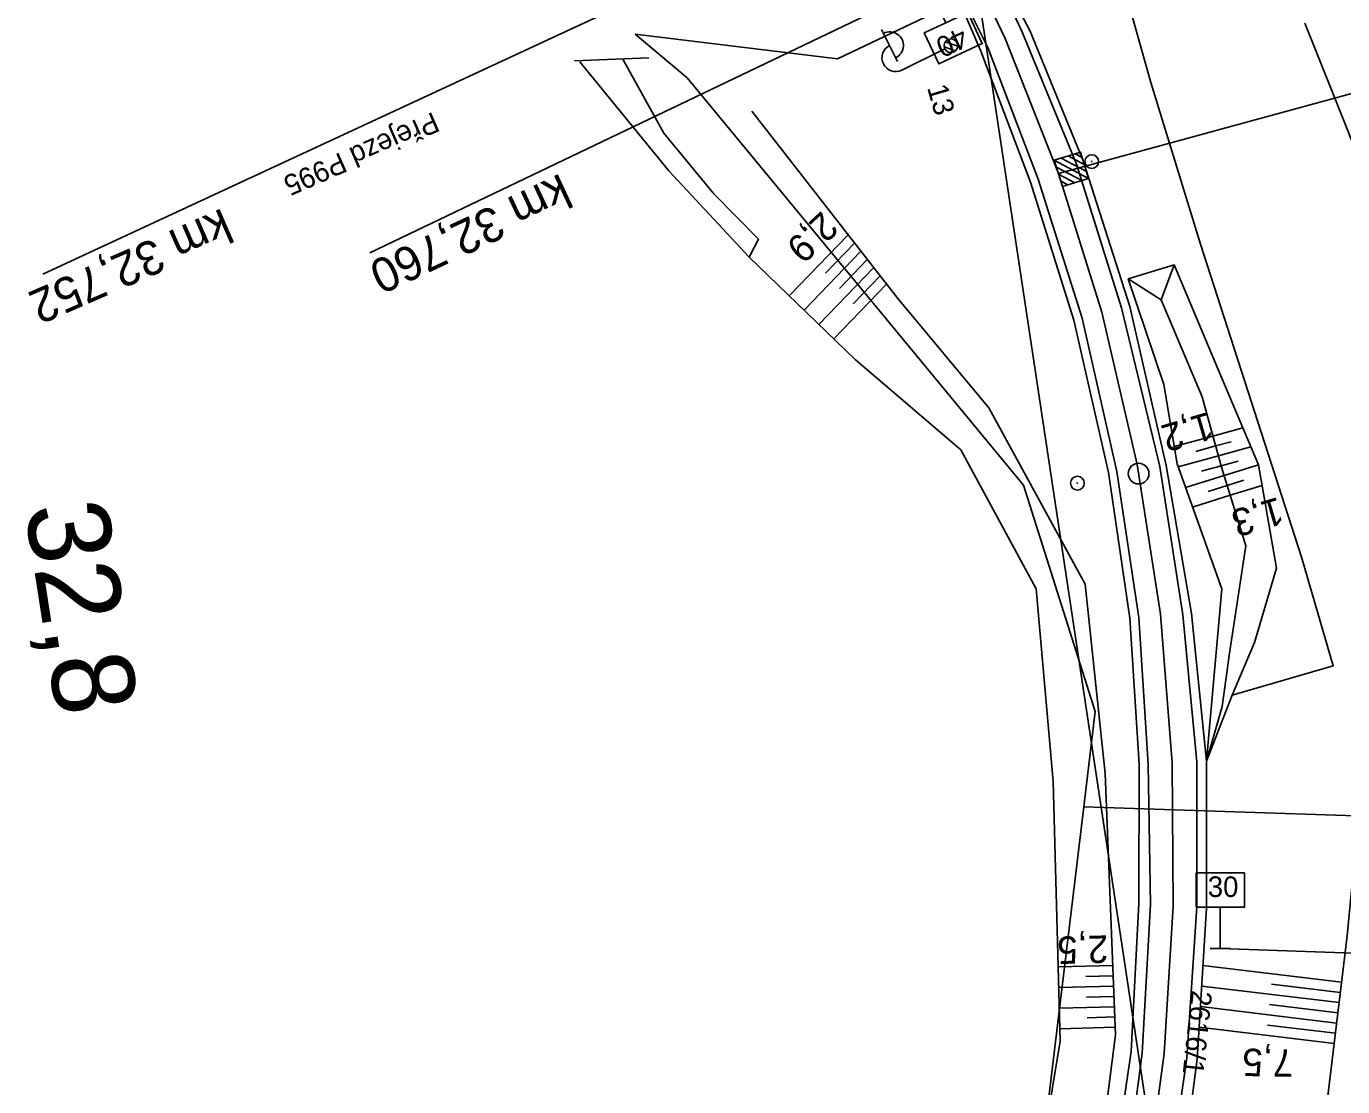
# Model space of a CAD drawing. Extents: x -804166 to -803706, y -1151030 to -1150147.
# Drawn here: x -803941 to -803845.1, y -1150593.1 to -1150515.9 of the extents above; entities that cross this region are included whole.
import ezdxf

# ---------------------------------------------------------------- set-up
doc = ezdxf.new("R2010")
doc.units = 0
for name, color, linetype in [('0381KM032-037P - Vrstva 1', 7, 'Continuous'), ('0381KM032-037P - Vrstva 16', 7, 'Continuous'), ('0381KM032-037P - Vrstva 25', 7, 'Continuous'), ('0381KM032-037P - Vrstva 27', 7, 'Continuous'), ('0381KM032-037P - Vrstva 3', 7, 'Continuous'), ('0381KM032-037P - Vrstva 4', 7, 'Continuous'), ('0381KM032-037P - Vrstva 48', 7, 'Continuous'), ('0381KM032-037P - Vrstva 49', 7, 'Continuous'), ('0381KM032-037P - Vrstva 5', 7, 'Continuous'), ('0381KM032-037P - Vrstva 50', 7, 'Continuous'), ('0381KM032-037P - Vrstva 55', 7, 'Continuous'), ('0381KM032-037P - Vrstva 57', 7, 'Continuous'), ('0381KM032-037P - Vrstva 7', 7, 'Continuous'), ('hran DP - hran DP', 7, 'Continuous'), ('vyt_sit - polygon', 7, 'Continuous')]:
    doc.layers.add(name, color=color, linetype=linetype)

msp = doc.modelspace()

# ---------------------------------------------------------------- linework, layer by layer
at = {"layer": '0381KM032-037P - Vrstva 1'}
for points in [[(-803874.069, -1150507.541), (-803869.666, -1150516.774), (-803865.801, -1150526.594), (-803862.645, -1150536.71)], [(-803862.645, -1150536.71), (-803860.057, -1150547.81), (-803858.364, -1150558.718), (-803857.51, -1150569.546), (-803857.425, -1150579.975), (-803858.096, -1150590.725), (-803859.58, -1150601.687), (-803861.73, -1150611.946), (-803864.691, -1150622.329), (-803868.306, -1150632.261), (-803873.118, -1150643.006), (-803878.784, -1150653.323), (-803884.455, -1150662.043), (-803890.68, -1150670.289), (-803894.474, -1150674.768)]]:
    msp.add_lwpolyline(points, dxfattribs=at)
at = {"layer": '0381KM032-037P - Vrstva 16'}
msp.add_line((-803901.044, -1150518.397), (-803895.63, -1150518.178), dxfattribs=at)
msp.add_lwpolyline([(-803888.331, -1150532.703), (-803887.637, -1150531.393), (-803890.889, -1150528.076), (-803894.531, -1150523.664), (-803897.525, -1150518.265)], dxfattribs=at)
at = {"layer": '0381KM032-037P - Vrstva 25'}
for p, q in [((-803877.522, -1150518.443), (-803878.676, -1150516.113)), ((-803873.129, -1150517.315), (-803874.036, -1150517.009)), ((-803874.075, -1150517.517), (-803877.211, -1150519.07)), ((-803873.284, -1150517.659), (-803874.117, -1150517.377))]:
    msp.add_line(p, q, dxfattribs=at)
msp.add_circle((-803873.627, -1150517.295), 0.5, dxfattribs=at)
msp.add_circle((-803873.627, -1150517.295), 0.5, dxfattribs=at)
for centre, start, end in [((-803878.088, -1150517.273), 295.64486, 117.05001), ((-803877.655, -1150518.174), 116.34744, 296.34744)]:
    msp.add_arc(centre, 1, start, end, dxfattribs=at)
at = {"layer": '0381KM032-037P - Vrstva 27'}
msp.add_line((-803863.381, -1150525.682), (-803863.351, -1150525.778), dxfattribs=at)
msp.add_circle((-803863.366, -1150525.73), 0.5, dxfattribs=at)
at = {"layer": '0381KM032-037P - Vrstva 3'}
for p, q in [((-803865.801, -1150526.594), (-803827.99, -1150516.298)), ((-803863.594, -1150526.953), (-803866.099, -1150525.639)), ((-803863.752, -1150526.447), (-803865.593, -1150525.482)), ((-803863.91, -1150525.94), (-803865.086, -1150525.323)), ((-803864.068, -1150525.434), (-803864.58, -1150525.166)), ((-803864.1, -1150527.111), (-803865.941, -1150526.145)), ((-803864.607, -1150527.269), (-803865.783, -1150526.652)), ((-803865.113, -1150527.427), (-803865.625, -1150527.158))]:
    msp.add_line(p, q, dxfattribs=at)
msp.add_lwpolyline([(-803865.503, -1150527.549), (-803866.099, -1150525.639), (-803864.19, -1150525.044), (-803863.594, -1150526.953)], close=True, dxfattribs=at)
at = {"layer": '0381KM032-037P - Vrstva 4'}
msp.add_line((-803875.88, -1150504.253), (-803939.777, -1150533.943), dxfattribs=at)
for points in [[(-803872.779, -1150506.875), (-803867.872, -1150516.171), (-803864.004, -1150525.679), (-803860.599, -1150536.286), (-803857.956, -1150547.888), (-803856.113, -1150558.65), (-803855.009, -1150569.422), (-803855.013, -1150580.14), (-803855.681, -1150591.137), (-803857.109, -1150602.102)], [(-803872.779, -1150506.875), (-803868.424, -1150516.34), (-803864.491, -1150525.922), (-803861.191, -1150536.397), (-803858.415, -1150547.949), (-803856.721, -1150558.765), (-803855.706, -1150569.464), (-803855.706, -1150580.041), (-803856.439, -1150591.045), (-803858.016, -1150602.009)], [(-803875.392, -1150508.511), (-803870.942, -1150517.43), (-803867.281, -1150527.019), (-803864.067, -1150537.143), (-803861.546, -1150548.304), (-803859.948, -1150558.943), (-803859.253, -1150569.653), (-803859.085, -1150579.867)], [(-803875.392, -1150508.511), (-803871.454, -1150517.68), (-803867.834, -1150527.236), (-803864.663, -1150537.291), (-803862.152, -1150548.382), (-803860.595, -1150558.999), (-803859.922, -1150569.628), (-803859.947, -1150579.801), (-803860.5, -1150590.58), (-803862.041, -1150601.171)], [(-803859.085, -1150579.867), (-803859.701, -1150590.693), (-803861.107, -1150601.386)]]:
    msp.add_lwpolyline(points, dxfattribs=at)
at = {"layer": '0381KM032-037P - Vrstva 48'}
for p, q in [((-803881.117, -1150531.067), (-803885.404, -1150535.52)), ((-803880.652, -1150531.665), (-803882.757, -1150533.853)), ((-803880.186, -1150532.262), (-803884.323, -1150536.561)), ((-803879.255, -1150533.458), (-803883.242, -1150537.601)), ((-803879.721, -1150532.86), (-803881.751, -1150534.97)), ((-803878.789, -1150534.056), (-803880.745, -1150536.088)), ((-803878.324, -1150534.653), (-803882.161, -1150538.641)), ((-803854.539, -1150545.729), (-803857.362, -1150546.5)), ((-803854.539, -1150545.729), (-803852.357, -1150545.132)), ((-803854.341, -1150546.452), (-803855.79, -1150546.848)), ((-803854.341, -1150546.452), (-803853.202, -1150546.141)), ((-803854.144, -1150547.176), (-803851.767, -1150546.526)), ((-803854.144, -1150547.176), (-803857.074, -1150547.977)), ((-803853.946, -1150547.899), (-803855.383, -1150548.292)), ((-803853.946, -1150547.899), (-803852.709, -1150547.561)), ((-803853.726, -1150548.616), (-803851.216, -1150547.835)), ((-803853.726, -1150548.616), (-803856.53, -1150549.489)), ((-803853.503, -1150549.332), (-803854.89, -1150549.764)), ((-803853.503, -1150549.332), (-803852.294, -1150548.956)), ((-803853.28, -1150550.048), (-803850.955, -1150549.325)), ((-803853.28, -1150550.048), (-803856.023, -1150550.902)), ((-803861.839, -1150584.311), (-803865.814, -1150584.417)), ((-803845.169, -1150585.523), (-803855.266, -1150584.307)), ((-803861.809, -1150585.06), (-803863.801, -1150585.114)), ((-803861.779, -1150585.81), (-803865.774, -1150585.917)), ((-803845.348, -1150587.012), (-803855.357, -1150585.806)), ((-803845.259, -1150586.267), (-803850.285, -1150585.662)), ((-803861.749, -1150586.559), (-803863.751, -1150586.613)), ((-803845.438, -1150587.757), (-803850.42, -1150587.157)), ((-803861.719, -1150587.309), (-803865.734, -1150587.416)), ((-803861.688, -1150588.058), (-803863.701, -1150588.112)), ((-803845.528, -1150588.501), (-803855.448, -1150587.306)), ((-803861.658, -1150588.808), (-803865.694, -1150588.916)), ((-803845.707, -1150589.991), (-803855.539, -1150588.806)), ((-803845.617, -1150589.246), (-803850.556, -1150588.651))]:
    msp.add_line(p, q, dxfattribs=at)
at = {"layer": '0381KM032-037P - Vrstva 49'}
for p, q in [((-803858.306, -1150535.807), (-803857.356, -1150533.258)), ((-803853.881, -1150556.86), (-803855.009, -1150569.422)), ((-803853.877, -1150565.433), (-803855.009, -1150569.422))]:
    msp.add_line(p, q, dxfattribs=at)
for points in [[(-803866.91, -1150495.141), (-803866.848, -1150501.095), (-803862.336, -1150508.281), (-803859.067, -1150519.976)], [(-803859.067, -1150519.976), (-803855.447, -1150531.748), (-803848.057, -1150554.624), (-803845.788, -1150562.48), (-803853.14, -1150564.614), (-803855.009, -1150569.422)], [(-803888.13, -1150522.065), (-803877.502, -1150535.708), (-803870.854, -1150543.675), (-803863.849, -1150556.524), (-803862.399, -1150570.315), (-803861.636, -1150589.369), (-803863.02, -1150600.178)], [(-803888.331, -1150532.703), (-803880.592, -1150540.151), (-803872.905, -1150546.743), (-803867.412, -1150556.856), (-803866.176, -1150570.896), (-803865.67, -1150589.811), (-803867.321, -1150599.808), (-803870.937, -1150611.902)], [(-803854.155, -1150540.878), (-803857.356, -1150533.258), (-803860.708, -1150534.282), (-803858.11, -1150541.981)], [(-803855.323, -1150542.862), (-803858.306, -1150535.807), (-803860.708, -1150534.282)], [(-803854.155, -1150540.878), (-803851.218, -1150547.825), (-803849.897, -1150555.364)], [(-803853.881, -1150556.86), (-803857.154, -1150547.754), (-803858.11, -1150541.981)], [(-803855.323, -1150542.862), (-803853.921, -1150547.99), (-803852.134, -1150553.731)], [(-803852.134, -1150553.731), (-803853.332, -1150561.547), (-803853.877, -1150565.433)], [(-803849.897, -1150555.364), (-803851.515, -1150560.763), (-803853.14, -1150564.614)], [(-803838.825, -1150566.88), (-803844.043, -1150574.496), (-803844.762, -1150582.145), (-803846.556, -1150597.039), (-803847.173, -1150599.748), (-803857.384, -1150629.008)], [(-803855.009, -1150569.422), (-803855.013, -1150580.14), (-803855.681, -1150591.137), (-803857.109, -1150602.102), (-803859.611, -1150612.518), (-803862.49, -1150623.34), (-803866.1, -1150633.182), (-803870.873, -1150644.181), (-803876.806, -1150654.687), (-803882.51, -1150663.405)]]:
    msp.add_lwpolyline(points, dxfattribs=at)
at = {"layer": '0381KM032-037P - Vrstva 5'}
for p, q in [((-803875.265, -1150512.897), (-803915.956, -1150532.369)), ((-803854.751, -1150583.067), (-803853.251, -1150583.067)), ((-803854.001, -1150583.067), (-803809.398, -1150584.605))]:
    msp.add_line(p, q, dxfattribs=at)
for points in [[(-803875.265, -1150512.897), (-803873.991, -1150515.613), (-803875.575, -1150516.356), (-803874.513, -1150518.62), (-803871.345, -1150517.133), (-803872.407, -1150514.87), (-803873.991, -1150515.613)], [(-803854.001, -1150583.067), (-803854.001, -1150580.067), (-803852.251, -1150580.067), (-803852.251, -1150577.567), (-803855.751, -1150577.567), (-803855.751, -1150580.067), (-803854.001, -1150580.067)]]:
    msp.add_lwpolyline(points, dxfattribs=at)
at = {"layer": '0381KM032-037P - Vrstva 50'}
msp.add_lwpolyline([(-803870.937, -1150611.902), (-803867.321, -1150599.808), (-803865.67, -1150589.811), (-803866.176, -1150570.896), (-803867.412, -1150556.856), (-803872.905, -1150546.743), (-803880.592, -1150540.151), (-803888.331, -1150532.703), (-803894.19, -1150526.416), (-803900.653, -1150518.475)], dxfattribs=at)
at = {"layer": '0381KM032-037P - Vrstva 55'}
msp.add_line((-803863.95, -1150572.75), (-803843.4, -1150573.43), dxfattribs=at)
at = {"layer": '0381KM032-037P - Vrstva 7'}
msp.add_line((-803864.421, -1150549.114), (-803864.405, -1150549.212), dxfattribs=at)
for centre, radius in [((-803859.955, -1150548.467), 0.75), ((-803864.413, -1150549.163), 0.5)]:
    msp.add_circle(centre, radius, dxfattribs=at)
at = {"layer": 'hran DP - hran DP'}
for p, q in [((-803881.88, -1150518.24), (-803874.06, -1150514.53)), ((-803847.85, -1150515.64), (-803845.22, -1150522.21)), ((-803892.84, -1150519.63), (-803896.64, -1150516.44)), ((-803896.64, -1150516.44), (-803881.88, -1150518.24)), ((-803868.33, -1150549.32), (-803892.84, -1150519.63)), ((-803845.22, -1150522.21), (-803843.61, -1150526.23)), ((-803863.11, -1150565.8), (-803868.33, -1150549.32)), ((-803863.95, -1150572.75), (-803863.11, -1150565.8)), ((-803868.49, -1150610.44), (-803863.95, -1150572.75))]:
    msp.add_line(p, q, dxfattribs=at)
at = {"layer": 'vyt_sit - polygon'}
msp.add_line((-803857.351, -1150608.078), (-803872.981, -1150504.591), dxfattribs=at)

# ---------------------------------------------------------------- texts
at = {"layer": '0381KM032-037P - Vrstva 25'}
msp.add_text('13', height=1.5, rotation=286.34744, dxfattribs=at).set_placement((-803875.377, -1150520.344))
at = {"layer": '0381KM032-037P - Vrstva 4'}
for s, height, p in [('Přejezd P995', 1.5, (-803911.348, -1150522.078)), ('km 32,752', 2.5, (-803926.702, -1150529.095))]:
    msp.add_text(s, height=height, rotation=203.59524, dxfattribs=at).set_placement(p)
at = {"layer": '0381KM032-037P - Vrstva 48'}
for s, rotation, p in [('2,9', 222.91886, (-803883.021, -1150529.264)), ('1,2', 196.35186, (-803854.887, -1150543.961)), ('1,3', 196.38012, (-803849.768, -1150550.152)), ('2,5', 181.53237, (-803862.191, -1150582.109)), ('7,5', 179.00475, (-803848.659, -1150590.424))]:
    msp.add_text(s, height=2, rotation=rotation, dxfattribs=at).set_placement(p)
at = {"layer": '0381KM032-037P - Vrstva 5'}
for s, height, p in [('40', 1.5, (-803872.846, -1150515.904)), ('km 32,760', 2.5, (-803902.064, -1150526.559))]:
    msp.add_text(s, height=height, rotation=205.13221, dxfattribs=at).set_placement(p)
msp.add_text('30', height=1.5, dxfattribs=at).set_placement((-803854.914, -1150579.317))
at = {"layer": '0381KM032-037P - Vrstva 57'}
msp.add_text('2616/1', height=1.5, rotation=263.79604, dxfattribs=at).set_placement((-803856.079, -1150586.074))
at = {"layer": '0381KM032-037P - Vrstva 7'}
msp.add_text('32,8', height=6, rotation=278.82233, dxfattribs=at).set_placement((-803941.117, -1150550.923))

doc.saveas('drawing.dxf')
